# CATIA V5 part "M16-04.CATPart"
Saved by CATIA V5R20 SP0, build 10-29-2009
Part number: M16-04
Revision: ANY
Definition: UNKNOWN
Nomenclature: M16-04
Source: Unknown
Bounding box of the stored display mesh (mm): x -32.5 to 32.5, y -32.322 to 32.322, z 0 to 6
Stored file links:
  C:\Users\Utente\Desktop\IO LAVORO\3D X SITO CF\X 3D SITO CF 27-09-2020\740T\M16-04.CATPart
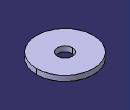
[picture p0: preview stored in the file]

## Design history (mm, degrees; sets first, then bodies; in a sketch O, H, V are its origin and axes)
Body1 "NONE" (main body)
  Solid1: solid without history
